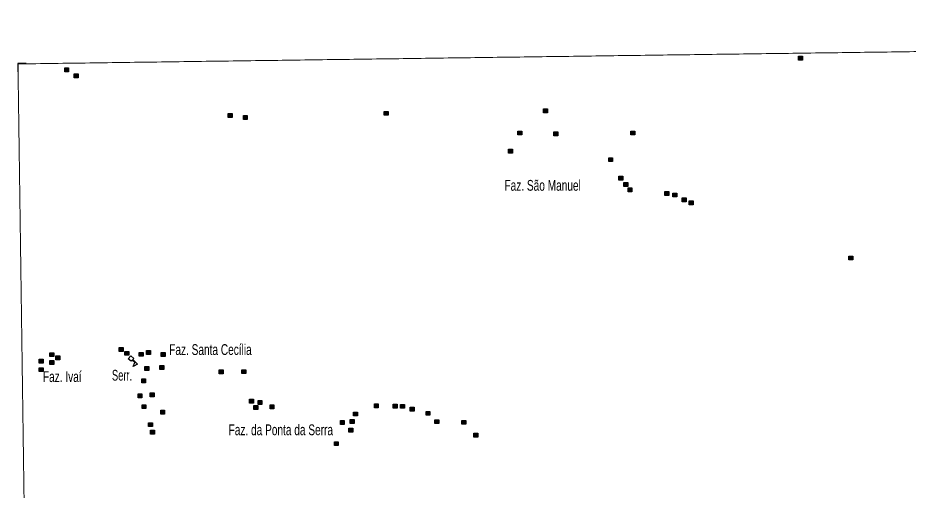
# Model space of a CAD drawing. Extents: x 265.7 to 292.1, y 7676.2 to 7704.2.
# Drawn here: x 265.72 to 272.32, y 7700.7 to 7704.2 of the extents above; entities that cross this region are included whole.
import ezdxf

# ---------------------------------------------------------------- set-up
doc = ezdxf.new("R2010")
doc.units = 0
doc.header["$LTSCALE"] = 0.032
for name, color, linetype, lineweight in [('2', 7, 'Continuous', 25), ('4', 7, 'Continuous', 25), ('63', 7, 'Continuous', 13)]:
    doc.layers.add(name, color=color, linetype=linetype, lineweight=lineweight)
doc.layers.add('61', color=7, linetype='Continuous')

msp = doc.modelspace()

# ---------------------------------------------------------------- hatches: boundary and pattern name
at = {"layer": '2'}
for points in [[(271.5053, 7703.9186), (271.5343, 7703.9186), (271.5343, 7703.8896), (271.5053, 7703.8896)], [(266.0642, 7703.8315), (266.0932, 7703.8315), (266.0932, 7703.8025), (266.0642, 7703.8025)], [(266.1343, 7703.7864), (266.1633, 7703.7864), (266.1633, 7703.7574), (266.1343, 7703.7574)], [(267.2764, 7703.4934), (267.3054, 7703.4934), (267.3054, 7703.4644), (267.2764, 7703.4644)], [(268.4337, 7703.5087), (268.4627, 7703.5087), (268.4627, 7703.4797), (268.4337, 7703.4797)], [(269.6144, 7703.5265), (269.6434, 7703.5265), (269.6434, 7703.4975), (269.6144, 7703.4975)], [(267.3894, 7703.4772), (267.4184, 7703.4772), (267.4184, 7703.4482), (267.3894, 7703.4482)], [(269.424, 7703.3627), (269.453, 7703.3627), (269.453, 7703.3337), (269.424, 7703.3337)], [(270.2624, 7703.3626), (270.2914, 7703.3626), (270.2914, 7703.3336), (270.2624, 7703.3336)], [(269.6911, 7703.3569), (269.7201, 7703.3569), (269.7201, 7703.3279), (269.6911, 7703.3279)], [(269.3553, 7703.2287), (269.3843, 7703.2287), (269.3843, 7703.1997), (269.3553, 7703.1997)], [(270.0979, 7703.165), (270.1269, 7703.165), (270.1269, 7703.136), (270.0979, 7703.136)], [(270.1737, 7703.0277), (270.2027, 7703.0277), (270.2027, 7702.9987), (270.1737, 7702.9987)], [(270.2101, 7702.9801), (270.2391, 7702.9801), (270.2391, 7702.9511), (270.2101, 7702.9511)], [(270.2415, 7702.9413), (270.2705, 7702.9413), (270.2705, 7702.9123), (270.2415, 7702.9123)], [(270.5151, 7702.9132), (270.5441, 7702.9132), (270.5441, 7702.8842), (270.5151, 7702.8842)], [(270.5732, 7702.9027), (270.6022, 7702.9027), (270.6022, 7702.8737), (270.5732, 7702.8737)], [(270.6435, 7702.8671), (270.6725, 7702.8671), (270.6725, 7702.8381), (270.6435, 7702.8381)], [(270.6951, 7702.8453), (270.7241, 7702.8453), (270.7241, 7702.8163), (270.6951, 7702.8163)], [(271.8791, 7702.4353), (271.9081, 7702.4353), (271.9081, 7702.4063), (271.8791, 7702.4063)], [(265.9536, 7701.7179), (265.9826, 7701.7179), (265.9826, 7701.6889), (265.9536, 7701.6889)], [(266.4686, 7701.7565), (266.4976, 7701.7565), (266.4976, 7701.7275), (266.4686, 7701.7275)], [(266.5113, 7701.7276), (266.5403, 7701.7276), (266.5403, 7701.6986), (266.5113, 7701.6986)], [(266.6171, 7701.7202), (266.6461, 7701.7202), (266.6461, 7701.6912), (266.6171, 7701.6912)], [(266.6703, 7701.7348), (266.6993, 7701.7348), (266.6993, 7701.7058), (266.6703, 7701.7058)], [(266.7801, 7701.7186), (266.8091, 7701.7186), (266.8091, 7701.6896), (266.7801, 7701.6896)], [(265.8761, 7701.6703), (265.9051, 7701.6703), (265.9051, 7701.6413), (265.8761, 7701.6413)], [(265.9544, 7701.659), (265.9834, 7701.659), (265.9834, 7701.63), (265.9544, 7701.63)], [(265.9979, 7701.6936), (266.0269, 7701.6936), (266.0269, 7701.6646), (265.9979, 7701.6646)], [(265.8757, 7701.6068), (265.9047, 7701.6068), (265.9047, 7701.5778), (265.8757, 7701.5778)], [(266.659, 7701.6146), (266.688, 7701.6146), (266.688, 7701.5856), (266.659, 7701.5856)], [(266.7703, 7701.6218), (266.7993, 7701.6218), (266.7993, 7701.5928), (266.7703, 7701.5928)], [(267.2094, 7701.5903), (267.2384, 7701.5903), (267.2384, 7701.5613), (267.2094, 7701.5613)], [(267.3781, 7701.592), (267.4071, 7701.592), (267.4071, 7701.563), (267.3781, 7701.563)], [(266.6354, 7701.524), (266.6644, 7701.524), (266.6644, 7701.495), (266.6354, 7701.495)], [(266.6081, 7701.412), (266.6371, 7701.412), (266.6371, 7701.383), (266.6081, 7701.383)], [(266.6978, 7701.4201), (266.7268, 7701.4201), (266.7268, 7701.3911), (266.6978, 7701.3911)], [(266.638, 7701.3321), (266.667, 7701.3321), (266.667, 7701.3031), (266.638, 7701.3031)], [(267.4346, 7701.3733), (267.4636, 7701.3733), (267.4636, 7701.3443), (267.4346, 7701.3443)], [(267.4661, 7701.3265), (267.4951, 7701.3265), (267.4951, 7701.2975), (267.4661, 7701.2975)], [(267.4979, 7701.3637), (267.5269, 7701.3637), (267.5269, 7701.3347), (267.4979, 7701.3347)], [(267.587, 7701.3312), (267.616, 7701.3312), (267.616, 7701.3022), (267.587, 7701.3022)], [(268.3603, 7701.3377), (268.3893, 7701.3377), (268.3893, 7701.3087), (268.3603, 7701.3087)], [(268.5006, 7701.3362), (268.5296, 7701.3362), (268.5296, 7701.3072), (268.5006, 7701.3072)], [(268.554, 7701.3346), (268.583, 7701.3346), (268.583, 7701.3056), (268.554, 7701.3056)], [(268.6258, 7701.3143), (268.6548, 7701.3143), (268.6548, 7701.2853), (268.6258, 7701.2853)], [(266.776, 7701.2918), (266.805, 7701.2918), (266.805, 7701.2628), (266.776, 7701.2628)], [(268.206, 7701.2773), (268.235, 7701.2773), (268.235, 7701.2483), (268.206, 7701.2483)], [(268.7437, 7701.2829), (268.7727, 7701.2829), (268.7727, 7701.2539), (268.7437, 7701.2539)], [(266.6856, 7701.1982), (266.7146, 7701.1982), (266.7146, 7701.1692), (266.6856, 7701.1692)], [(268.1084, 7701.2151), (268.1374, 7701.2151), (268.1374, 7701.1861), (268.1084, 7701.1861)], [(268.1819, 7701.2215), (268.2109, 7701.2215), (268.2109, 7701.1925), (268.1819, 7701.1925)], [(268.8098, 7701.2208), (268.8388, 7701.2208), (268.8388, 7701.1918), (268.8098, 7701.1918)], [(269.009, 7701.2159), (269.038, 7701.2159), (269.038, 7701.1869), (269.009, 7701.1869)], [(266.701, 7701.1424), (266.73, 7701.1424), (266.73, 7701.1134), (266.701, 7701.1134)], [(268.1722, 7701.157), (268.2012, 7701.157), (268.2012, 7701.128), (268.1722, 7701.128)], [(269.0979, 7701.1208), (269.1269, 7701.1208), (269.1269, 7701.0918), (269.0979, 7701.0918)], [(268.0641, 7701.0577), (268.0931, 7701.0577), (268.0931, 7701.0287), (268.0641, 7701.0287)]]:
    msp.add_hatch(color=256, dxfattribs=at).paths.add_polyline_path(points)

# ---------------------------------------------------------------- linework, layer by layer
for points in [[(271.5053, 7703.9186), (271.5343, 7703.9186), (271.5343, 7703.8896), (271.5053, 7703.8896)], [(266.0642, 7703.8315), (266.0932, 7703.8315), (266.0932, 7703.8025), (266.0642, 7703.8025)], [(266.1343, 7703.7864), (266.1633, 7703.7864), (266.1633, 7703.7574), (266.1343, 7703.7574)], [(267.2764, 7703.4934), (267.3054, 7703.4934), (267.3054, 7703.4644), (267.2764, 7703.4644)], [(268.4337, 7703.5087), (268.4627, 7703.5087), (268.4627, 7703.4797), (268.4337, 7703.4797)], [(269.6144, 7703.5265), (269.6434, 7703.5265), (269.6434, 7703.4975), (269.6144, 7703.4975)], [(267.3894, 7703.4772), (267.4184, 7703.4772), (267.4184, 7703.4482), (267.3894, 7703.4482)], [(269.424, 7703.3627), (269.453, 7703.3627), (269.453, 7703.3337), (269.424, 7703.3337)], [(270.2624, 7703.3626), (270.2914, 7703.3626), (270.2914, 7703.3336), (270.2624, 7703.3336)], [(269.6911, 7703.3569), (269.7201, 7703.3569), (269.7201, 7703.3279), (269.6911, 7703.3279)], [(269.3553, 7703.2287), (269.3843, 7703.2287), (269.3843, 7703.1997), (269.3553, 7703.1997)], [(270.0979, 7703.165), (270.1269, 7703.165), (270.1269, 7703.136), (270.0979, 7703.136)], [(270.1737, 7703.0277), (270.2027, 7703.0277), (270.2027, 7702.9987), (270.1737, 7702.9987)], [(270.2101, 7702.9801), (270.2391, 7702.9801), (270.2391, 7702.9511), (270.2101, 7702.9511)], [(270.2415, 7702.9413), (270.2705, 7702.9413), (270.2705, 7702.9123), (270.2415, 7702.9123)], [(270.5151, 7702.9132), (270.5441, 7702.9132), (270.5441, 7702.8842), (270.5151, 7702.8842)], [(270.5732, 7702.9027), (270.6022, 7702.9027), (270.6022, 7702.8737), (270.5732, 7702.8737)], [(270.6435, 7702.8671), (270.6725, 7702.8671), (270.6725, 7702.8381), (270.6435, 7702.8381)], [(270.6951, 7702.8453), (270.7241, 7702.8453), (270.7241, 7702.8163), (270.6951, 7702.8163)], [(271.8791, 7702.4353), (271.9081, 7702.4353), (271.9081, 7702.4063), (271.8791, 7702.4063)], [(265.9536, 7701.7179), (265.9826, 7701.7179), (265.9826, 7701.6889), (265.9536, 7701.6889)], [(266.4686, 7701.7565), (266.4976, 7701.7565), (266.4976, 7701.7275), (266.4686, 7701.7275)], [(266.5113, 7701.7276), (266.5403, 7701.7276), (266.5403, 7701.6986), (266.5113, 7701.6986)], [(266.6171, 7701.7202), (266.6461, 7701.7202), (266.6461, 7701.6912), (266.6171, 7701.6912)], [(266.6703, 7701.7348), (266.6993, 7701.7348), (266.6993, 7701.7058), (266.6703, 7701.7058)], [(266.7801, 7701.7186), (266.8091, 7701.7186), (266.8091, 7701.6896), (266.7801, 7701.6896)], [(265.8761, 7701.6703), (265.9051, 7701.6703), (265.9051, 7701.6413), (265.8761, 7701.6413)], [(265.9544, 7701.659), (265.9834, 7701.659), (265.9834, 7701.63), (265.9544, 7701.63)], [(265.9979, 7701.6936), (266.0269, 7701.6936), (266.0269, 7701.6646), (265.9979, 7701.6646)], [(265.8757, 7701.6068), (265.9047, 7701.6068), (265.9047, 7701.5778), (265.8757, 7701.5778)], [(266.659, 7701.6146), (266.688, 7701.6146), (266.688, 7701.5856), (266.659, 7701.5856)], [(266.7703, 7701.6218), (266.7993, 7701.6218), (266.7993, 7701.5928), (266.7703, 7701.5928)], [(267.2094, 7701.5903), (267.2384, 7701.5903), (267.2384, 7701.5613), (267.2094, 7701.5613)], [(267.3781, 7701.592), (267.4071, 7701.592), (267.4071, 7701.563), (267.3781, 7701.563)], [(266.6354, 7701.524), (266.6644, 7701.524), (266.6644, 7701.495), (266.6354, 7701.495)], [(266.6081, 7701.412), (266.6371, 7701.412), (266.6371, 7701.383), (266.6081, 7701.383)], [(266.6978, 7701.4201), (266.7268, 7701.4201), (266.7268, 7701.3911), (266.6978, 7701.3911)], [(266.638, 7701.3321), (266.667, 7701.3321), (266.667, 7701.3031), (266.638, 7701.3031)], [(267.4346, 7701.3733), (267.4636, 7701.3733), (267.4636, 7701.3443), (267.4346, 7701.3443)], [(267.4661, 7701.3265), (267.4951, 7701.3265), (267.4951, 7701.2975), (267.4661, 7701.2975)], [(267.4979, 7701.3637), (267.5269, 7701.3637), (267.5269, 7701.3347), (267.4979, 7701.3347)], [(267.587, 7701.3312), (267.616, 7701.3312), (267.616, 7701.3022), (267.587, 7701.3022)], [(268.3603, 7701.3377), (268.3893, 7701.3377), (268.3893, 7701.3087), (268.3603, 7701.3087)], [(268.5006, 7701.3362), (268.5296, 7701.3362), (268.5296, 7701.3072), (268.5006, 7701.3072)], [(268.554, 7701.3346), (268.583, 7701.3346), (268.583, 7701.3056), (268.554, 7701.3056)], [(268.6258, 7701.3143), (268.6548, 7701.3143), (268.6548, 7701.2853), (268.6258, 7701.2853)], [(266.776, 7701.2918), (266.805, 7701.2918), (266.805, 7701.2628), (266.776, 7701.2628)], [(268.206, 7701.2773), (268.235, 7701.2773), (268.235, 7701.2483), (268.206, 7701.2483)], [(268.7437, 7701.2829), (268.7727, 7701.2829), (268.7727, 7701.2539), (268.7437, 7701.2539)], [(266.6856, 7701.1982), (266.7146, 7701.1982), (266.7146, 7701.1692), (266.6856, 7701.1692)], [(268.1084, 7701.2151), (268.1374, 7701.2151), (268.1374, 7701.1861), (268.1084, 7701.1861)], [(268.1819, 7701.2215), (268.2109, 7701.2215), (268.2109, 7701.1925), (268.1819, 7701.1925)], [(268.8098, 7701.2208), (268.8388, 7701.2208), (268.8388, 7701.1918), (268.8098, 7701.1918)], [(269.009, 7701.2159), (269.038, 7701.2159), (269.038, 7701.1869), (269.009, 7701.1869)], [(266.701, 7701.1424), (266.73, 7701.1424), (266.73, 7701.1134), (266.701, 7701.1134)], [(268.1722, 7701.157), (268.2012, 7701.157), (268.2012, 7701.128), (268.1722, 7701.128)], [(269.0979, 7701.1208), (269.1269, 7701.1208), (269.1269, 7701.0918), (269.0979, 7701.0918)], [(268.0641, 7701.0577), (268.0931, 7701.0577), (268.0931, 7701.0287), (268.0641, 7701.0287)]]:
    msp.add_lwpolyline(points, close=True, dxfattribs=at)
at = {"layer": '4'}
for points in [[(266.5652, 7701.6629), (266.557, 7701.6541), (266.5356, 7701.6736), (266.5553, 7701.695), (266.5766, 7701.6754), (266.5685, 7701.6666)], [(266.5685, 7701.6666), (266.6042, 7701.6339), (266.5727, 7701.6167), (266.5844, 7701.6454), (266.5652, 7701.6629)]]:
    msp.add_lwpolyline(points, dxfattribs=at)
at = {"layer": '63', "lineweight": 25}
msp.add_lwpolyline([(265.7781, 7703.8633), (265.7165, 7703.8633), (265.7165, 7703.8026)], dxfattribs=at)
at = {"layer": '63'}
for points in [[(265.7179, 7703.8606), (266.2494, 7703.868), (266.7808, 7703.8754), (267.3123, 7703.8828), (267.8437, 7703.8901), (268.3752, 7703.8974), (268.9066, 7703.9047), (269.4381, 7703.912), (269.9695, 7703.9193), (270.501, 7703.9265), (271.0324, 7703.9338), (271.5639, 7703.941), (272.0953, 7703.9482), (272.6268, 7703.9554), (273.1582, 7703.9626), (273.6896, 7703.9697), (274.2211, 7703.9769), (274.7525, 7703.984), (275.2839, 7703.9911), (275.8154, 7703.9982), (276.3468, 7704.0052), (276.8782, 7704.0123), (277.4097, 7704.0193), (277.9411, 7704.0263), (278.4725, 7704.0333), (279.0039, 7704.0403), (279.5354, 7704.0473), (280.0668, 7704.0543), (280.5982, 7704.0612), (281.1296, 7704.0681), (281.661, 7704.075), (282.1925, 7704.0819), (282.7239, 7704.0888), (283.2553, 7704.0956), (283.7867, 7704.1025), (284.3181, 7704.1093), (284.8495, 7704.1161), (285.3809, 7704.1229), (285.9123, 7704.1296), (286.4437, 7704.1364), (286.9751, 7704.1431), (287.5065, 7704.1498), (288.0379, 7704.1565), (288.5693, 7704.1632), (289.1007, 7704.1699), (289.6321, 7704.1765), (290.1635, 7704.1832), (290.6949, 7704.1898), (291.2263, 7704.1964), (291.7577, 7704.203)], [(266.1055, 7676.1764), (266.0976, 7676.7414), (266.0896, 7677.3064), (266.0817, 7677.8713), (266.0737, 7678.4363), (266.0658, 7679.0013), (266.0578, 7679.5663), (266.0499, 7680.1313), (266.0419, 7680.6963), (266.034, 7681.2613), (266.026, 7681.8263), (266.0181, 7682.3913), (266.0102, 7682.9563), (266.0022, 7683.5212), (265.9943, 7684.0862), (265.9864, 7684.6512), (265.9785, 7685.2162), (265.9705, 7685.7812), (265.9626, 7686.3462), (265.9547, 7686.9112), (265.9468, 7687.4762), (265.9389, 7688.0411), (265.9309, 7688.6061), (265.923, 7689.1711), (265.9151, 7689.7361), (265.9072, 7690.3011), (265.8993, 7690.8661), (265.8914, 7691.4311), (265.8835, 7691.996), (265.8756, 7692.561), (265.8677, 7693.126), (265.8598, 7693.691), (265.8519, 7694.256), (265.844, 7694.821), (265.8361, 7695.3859), (265.8282, 7695.9509), (265.8203, 7696.5159), (265.8124, 7697.0809), (265.8045, 7697.6459), (265.7967, 7698.2108), (265.7888, 7698.7758), (265.7809, 7699.3408), (265.773, 7699.9058), (265.7651, 7700.4708), (265.7573, 7701.0357), (265.7494, 7701.6007), (265.7415, 7702.1657), (265.7337, 7702.7307), (265.7258, 7703.2957), (265.7179, 7703.8606)]]:
    msp.add_spline(points, degree=3, dxfattribs=at)

# ---------------------------------------------------------------- texts
at = {"layer": '61'}
for s, width, p in [('Faz. São Manuel', 0.7, (269.3252, 7702.9197)), ('Faz. Santa Cecília', 0.7, (266.839, 7701.7012)), ('Faz. Ivaí', 0.7, (265.9026, 7701.5004)), ('Serr.', 0.65, (266.4144, 7701.5108)), ('Faz. da Ponta da Serra', 0.7, (267.2796, 7701.1058))]:
    msp.add_text(s, height=0.08, dxfattribs=dict(at, width=width)).set_placement(p)

doc.saveas('drawing.dxf')
